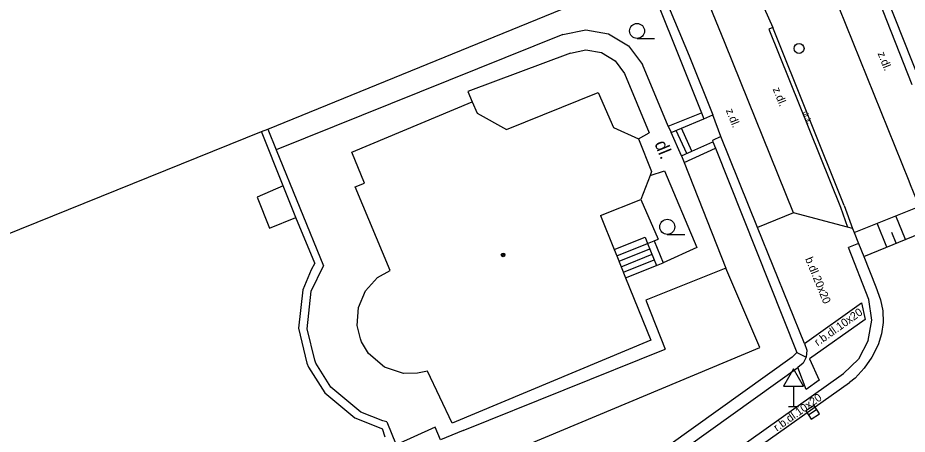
# Model space of a CAD drawing. Extents: x -600391 to -599491, y -1160176 to -1159402.
# Drawn here: x -599839.54 to -599795.12, y -1160142.59 to -1160121.8 of the extents above; entities that cross this region are included whole.
import ezdxf

# ---------------------------------------------------------------- set-up
doc = ezdxf.new("R2010")
doc.units = 0
for name, color, linetype in [('Level 10', 7, 'Continuous'), ('Level 11', 7, 'Continuous'), ('Level 15', 7, 'Continuous'), ('Level 27', 7, 'Continuous'), ('Level 28', 7, 'Continuous'), ('Level 34', 7, 'Continuous'), ('Level 36', 7, 'Continuous'), ('Level 39', 7, 'Continuous'), ('Level 40', 7, 'Continuous'), ('Level 5', 7, 'Continuous'), ('Level 51', 7, 'Continuous'), ('Level 7', 7, 'Continuous'), ('Level 8', 7, 'Continuous')]:
    doc.layers.add(name, color=color, linetype=linetype)

msp = doc.modelspace()

# ---------------------------------------------------------------- linework, layer by layer
at = {"layer": 'Level 10'}
for points in [[(-599804.2, -1160123.08), (-599808.18, -1160113.34)], [(-599798.53, -1160121.29), (-599795.03, -1160129.94), (-599794.96, -1160130.12), (-599794.51, -1160131.22), (-599794.47, -1160131.32), (-599794.36, -1160131.6), (-599794.08, -1160132.34), (-599794.06, -1160132.4), (-599793.9, -1160132.81)], [(-599800.79, -1160131.54), (-599804.2, -1160123.08)], [(-599797.85, -1160132.32), (-599798.09, -1160132.26), (-599800.79, -1160131.54)], [(-599797.85, -1160132.32), (-599797.76, -1160132.52), (-599797.54, -1160133.08), (-599797.28, -1160133.72), (-599796.69, -1160135.23)], [(-599796.69, -1160135.23), (-599796.45, -1160135.88), (-599796.33, -1160136.44), (-599796.32, -1160137.02), (-599796.4, -1160137.59), (-599796.57, -1160138.14)], [(-599796.57, -1160138.14), (-599796.88, -1160138.74), (-599797.26, -1160139.29), (-599797.71, -1160139.79), (-599798, -1160140.01)], [(-599802.86, -1160143.46), (-599798, -1160140.01)]]:
    msp.add_lwpolyline(points, dxfattribs=at)
at = {"layer": 'Level 11'}
for points in [[(-599806.203, -1160112.492), (-599801.83, -1160122.29)], [(-599812.31, -1160122.64), (-599811.17, -1160122.41), (-599810.03, -1160122.61), (-599809.03, -1160123.21), (-599808.33, -1160124.14)], [(-599801.83, -1160122.29), (-599802.02, -1160122.37)], [(-599802.02, -1160122.37), (-599798.45, -1160131.25), (-599798.09, -1160132.26)], [(-599798.26, -1160131.18), (-599801.83, -1160122.29)], [(-599812.31, -1160122.64), (-599826.64, -1160128.39)], [(-599811.93, -1160123.57), (-599817.06, -1160125.49), (-599816.84, -1160126)], [(-599811.93, -1160123.57), (-599811.16, -1160123.41), (-599810.38, -1160123.54), (-599809.7, -1160123.95), (-599809.23, -1160124.59)], [(-599807.05, -1160127.21), (-599808.33, -1160124.14)], [(-599809.23, -1160124.59), (-599808.01, -1160127.55)], [(-599808.53, -1160127.84), (-599808.01, -1160127.55)], [(-599806.39, -1160128.69), (-599806.91, -1160127.53)], [(-599806.13, -1160128.58), (-599806.65, -1160127.43)], [(-599805.88, -1160128.46), (-599806.39, -1160127.32)], [(-599806.26, -1160129.02), (-599804.18, -1160134.3)], [(-599807.96, -1160129.67), (-599807.24, -1160129.45)], [(-599807.24, -1160129.45), (-599805.63, -1160133.27)], [(-599798.26, -1160131.18), (-599797.85, -1160132.32)], [(-599797.76, -1160132.52), (-599794.51, -1160131.22)], [(-599800.79, -1160131.54), (-599802.59, -1160132.28)], [(-599797.28, -1160133.72), (-599794.06, -1160132.4)], [(-599797.54, -1160133.08), (-599798.05, -1160133.28)], [(-599809.51, -1160133.96), (-599807.97, -1160133.34)], [(-599805.63, -1160133.27), (-599807.31, -1160134.04)], [(-599797.03, -1160135.87), (-599798.05, -1160133.28)], [(-599809.4, -1160134.24), (-599807.86, -1160133.61)], [(-599809.29, -1160134.51), (-599807.75, -1160133.89)], [(-599819.71, -1160145.47), (-599802.47, -1160138.26), (-599804.18, -1160134.3)], [(-599809.18, -1160134.79), (-599807.64, -1160134.17)], [(-599804.18, -1160134.3), (-599808.17, -1160135.9)], [(-599808.17, -1160135.9), (-599807.21, -1160138.34)], [(-599800.24, -1160138.07), (-599797.4, -1160136.04), (-599797.21, -1160136.86), (-599800, -1160138.83), (-599799.51, -1160139.89), (-599800.17, -1160140.37), (-599800.58, -1160139.26)], [(-599796.88, -1160136.9), (-599797.03, -1160135.87)], [(-599797.06, -1160137.92), (-599796.88, -1160136.9)], [(-599797.06, -1160137.92), (-599797.55, -1160138.84), (-599798.3, -1160139.56)], [(-599817.3, -1160142.41), (-599807.21, -1160138.34)], [(-599803.78, -1160143.45), (-599798.3, -1160139.56)], [(-599817.3, -1160142.41), (-599818.43, -1160142.88), (-599818.7, -1160142.25), (-599820.65, -1160143.12)]]:
    msp.add_lwpolyline(points, dxfattribs=at)
at = {"layer": 'Level 15'}
for points in [[(-599795.2, -1160132.87), (-599795.69, -1160131.69)], [(-599796.13, -1160133.25), (-599796.62, -1160132.06)], [(-599795.67, -1160133.06), (-599795.89, -1160132.53)]]:
    msp.add_lwpolyline(points, dxfattribs=at)
at = {"layer": 'Level 27'}
msp.add_line((-599799.631, -1160141.363), (-599800.049, -1160141.637), dxfattribs=at)
msp.add_lwpolyline([(-599799.768, -1160141.154), (-599800.186, -1160141.428), (-599799.912, -1160141.846), (-599799.494, -1160141.572)], close=True, dxfattribs=at)
at = {"layer": 'Level 28'}
msp.add_circle((-599800.52, -1160123.33), 0.25, dxfattribs=at)
at = {"layer": 'Level 34'}
for p, q in [((-599800.8, -1160140.192), (-599800.8, -1160141.21)), ((-599801.05, -1160141.21), (-599800.55, -1160141.21))]:
    msp.add_line(p, q, dxfattribs=at)
msp.add_lwpolyline([(-599801.3, -1160140.192), (-599800.3, -1160140.192), (-599800.8, -1160139.326)], close=True, dxfattribs=at)
at = {"layer": 'Level 36'}
for p, q in [((-599808.61, -1160122.835), (-599807.735, -1160122.835)), ((-599807.1, -1160132.615), (-599806.225, -1160132.615))]:
    msp.add_line(p, q, dxfattribs=at)
for centre in [(-599808.61, -1160122.46), (-599807.1, -1160132.24)]:
    msp.add_circle(centre, 0.375, dxfattribs=at)
at = {"layer": 'Level 39'}
for radius in [0.09, 0.0398]:
    msp.add_circle((-599815.3, -1160133.64), radius, dxfattribs=at)
at = {"layer": 'Level 5'}
for points in [[(-599815.13, -1160127.38), (-599810.56, -1160125.53)], [(-599810.56, -1160125.53), (-599809.78, -1160127.28)], [(-599822.86, -1160128.51), (-599816.84, -1160126)], [(-599816.84, -1160126), (-599816.6, -1160126.56)], [(-599816.6, -1160126.56), (-599815.13, -1160127.38)], [(-599809.78, -1160127.28), (-599808.53, -1160127.84)], [(-599808.53, -1160127.84), (-599807.89, -1160129.47)], [(-599822.23, -1160130.06), (-599822.86, -1160128.51)], [(-599807.89, -1160129.47), (-599807.96, -1160129.67), (-599808.42, -1160130.87)], [(-599822.69, -1160130.25), (-599822.23, -1160130.06)], [(-599820.95, -1160134.42), (-599822.69, -1160130.25)], [(-599810.43, -1160131.68), (-599808.42, -1160130.87)], [(-599808.42, -1160130.87), (-599807.55, -1160132.86)], [(-599810.43, -1160131.68), (-599809.75, -1160133.37), (-599809.62, -1160133.69)], [(-599809.75, -1160133.37), (-599808.21, -1160132.75)], [(-599809.62, -1160133.69), (-599808.08, -1160133.07), (-599807.75, -1160132.94), (-599807.55, -1160132.86)], [(-599808.21, -1160132.75), (-599808.08, -1160133.07)], [(-599809.62, -1160133.69), (-599809.18, -1160134.79), (-599807.92, -1160137.9)], [(-599822.18, -1160135.44), (-599821.57, -1160134.77)], [(-599821.57, -1160134.77), (-599820.95, -1160134.42)], [(-599822.52, -1160136.26), (-599822.18, -1160135.44)], [(-599822.59, -1160137.16), (-599822.52, -1160136.26)], [(-599822.43, -1160137.84), (-599822.59, -1160137.16)], [(-599822.37, -1160137.99), (-599822.43, -1160137.84)], [(-599807.92, -1160137.9), (-599817.85, -1160142.05)], [(-599822.03, -1160138.56), (-599822.37, -1160137.99)], [(-599821.23, -1160139.24), (-599822.03, -1160138.56)], [(-599820.28, -1160139.56), (-599821.23, -1160139.24)], [(-599819.57, -1160139.55), (-599820.28, -1160139.56)], [(-599819.07, -1160139.44), (-599819.57, -1160139.55)], [(-599817.85, -1160142.05), (-599819.07, -1160139.44)]]:
    msp.add_lwpolyline(points, dxfattribs=at)
at = {"layer": 'Level 51'}
for points in [[(-599844.24, -1160134.28), (-599827.37, -1160127.48)], [(-599827.37, -1160127.48), (-599827.06, -1160127.37)], [(-599826.28, -1160130.19), (-599827.37, -1160127.48)], [(-599827.06, -1160127.37), (-599826.64, -1160128.39), (-599824.28, -1160134.18)], [(-599826.28, -1160130.19), (-599827.58, -1160130.76)], [(-599825.66, -1160131.77), (-599826.28, -1160130.19)], [(-599827.58, -1160130.76), (-599826.97, -1160132.3)], [(-599826.97, -1160132.3), (-599825.66, -1160131.77)], [(-599824.7, -1160134.05), (-599825.66, -1160131.77)], [(-599824.89, -1160134.39), (-599825.3, -1160135.39)], [(-599824.7, -1160134.05), (-599824.89, -1160134.39)], [(-599824.88, -1160135.46), (-599824.28, -1160134.18)], [(-599825.3, -1160135.39), (-599825.52, -1160137.3)], [(-599825.08, -1160137.34), (-599824.88, -1160135.46)], [(-599825.52, -1160137.3), (-599825.1, -1160139.04)], [(-599824.71, -1160138.89), (-599825.08, -1160137.34)], [(-599825.1, -1160139.04), (-599825.02, -1160139.24)], [(-599825.02, -1160139.24), (-599824.21, -1160140.53)], [(-599824.65, -1160139.04), (-599824.71, -1160138.89)], [(-599823.91, -1160140.25), (-599824.65, -1160139.04)], [(-599824.21, -1160140.53), (-599822.7, -1160141.77)], [(-599822.41, -1160141.5), (-599823.91, -1160140.25)], [(-599821.31, -1160141.92), (-599822.41, -1160141.5)], [(-599822.7, -1160141.77), (-599821.33, -1160142.33)], [(-599821.11, -1160141.97), (-599821.31, -1160141.92)], [(-599821.11, -1160141.97), (-599820.65, -1160143.12), (-599819.71, -1160145.47), (-599819.07, -1160147.06)], [(-599821.19, -1160142.74), (-599821.33, -1160142.33)]]:
    msp.add_lwpolyline(points, dxfattribs=at)
at = {"layer": 'Level 7'}
for points in [[(-599827.06, -1160127.37), (-599808.16, -1160119.64)], [(-599808.16, -1160119.64), (-599806.69, -1160123.3), (-599805.39, -1160126.54), (-599805.27, -1160126.84)], [(-599807.77, -1160119.48), (-599806, -1160123.7), (-599804.82, -1160126.65)], [(-599794.87, -1160125.15), (-599796.54, -1160120.91)], [(-599794.46, -1160124.99), (-599796.14, -1160120.78)], [(-599807.05, -1160127.21), (-599805.39, -1160126.54)], [(-599806.91, -1160127.53), (-599806.39, -1160127.32), (-599805.27, -1160126.84), (-599804.82, -1160126.65)], [(-599807.05, -1160127.21), (-599806.91, -1160127.53)], [(-599804.43, -1160127.73), (-599804.84, -1160127.93)], [(-599800.24, -1160138.07), (-599802.59, -1160132.28), (-599804.43, -1160127.73)], [(-599806.39, -1160128.69), (-599805.88, -1160128.46), (-599804.82, -1160127.99)], [(-599804.84, -1160127.93), (-599804.82, -1160127.99), (-599804.69, -1160128.32), (-599800.63, -1160138.51)], [(-599806.26, -1160129.02), (-599804.69, -1160128.32)], [(-599806.39, -1160128.69), (-599806.26, -1160129.02)], [(-599808.08, -1160133.07), (-599807.64, -1160134.17)], [(-599807.75, -1160132.94), (-599807.31, -1160134.04)], [(-599807.64, -1160134.17), (-599807.31, -1160134.04)], [(-599800.24, -1160138.07), (-599800.13, -1160138.4), (-599800.16, -1160138.74)], [(-599800.63, -1160138.51), (-599800.86, -1160138.74), (-599826.86, -1160157.35)], [(-599800.63, -1160138.51), (-599800.16, -1160138.74)], [(-599800.16, -1160138.74), (-599800.32, -1160139.04), (-599800.58, -1160139.26)], [(-599817.08, -1160151.08), (-599800.58, -1160139.26)]]:
    msp.add_lwpolyline(points, dxfattribs=at)
at = {"layer": 'Level 8'}
msp.add_lwpolyline([(-599804.43, -1160127.73), (-599804.82, -1160126.65)], dxfattribs=at)

# ---------------------------------------------------------------- texts
at = {"layer": 'Level 40'}
for s, height, rotation, p in [('z.dl.', 0.4, 291.889, (-599796.6, -1160123.58)), ('z.dl.', 0.4, 291.889, (-599801.84, -1160125.36)), ('z.dl.', 0.4, 291.889, (-599804.18, -1160126.42)), ('dr.k.', 0.25, 292.3333, (-599800.33, -1160126.52)), ('dl.', 0.65, 292.3481, (-599807.75, -1160128.08)), ('b.dl.20x20', 0.4, 292.3333, (-599800.22, -1160133.84)), ('r.b.dl.10x20', 0.4, 35.43, (-599799.58, -1160138.21)), ('r.b.dl.10x20', 0.39997, 35.3645, (-599801.62, -1160142.47))]:
    msp.add_text(s, height=height, rotation=rotation, dxfattribs=at).set_placement(p)

doc.saveas('drawing.dxf')
